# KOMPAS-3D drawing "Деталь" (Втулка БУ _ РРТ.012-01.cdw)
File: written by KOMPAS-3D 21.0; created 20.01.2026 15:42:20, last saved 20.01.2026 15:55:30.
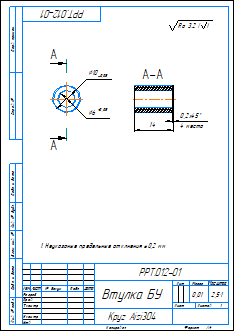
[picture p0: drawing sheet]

Sheet 1: A4, portrait

Document properties: Автор: Alexey; Масса: 0.005513; Полное имя файла: ..\Documents\Bitrix24\Производство\технологии\KazanTarget\эксперименты\ручной ротатор\РРТ.012-01 Втулка БУ\РРТ.012-01 Втулка БУ.m3d

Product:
- Part/product: Деталь
    Масса: 0.005513

Title block, sheet 1: Наименование: Втулка БУ; designation: РРТ.012-01; Материал: Круг Aisi304; Масса: 0,01; Количество листов документа: 1; Форматы листов документа: A4; stored path: C:\Users\Alexey\Desktop\Втулка БУ _ РРТ.012-01.cdw

Views: Вид 1, Слева, Разрез А-А
Referenced files in C:\Users\Alexey\Documents\Bitrix24\Производство\технологии\KazanTarget\эксперименты\ручной ротатор\РРТ.012-01 Втулка БУ\: РРТ.012-01 Втулка БУ.m3d
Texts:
  1. Неуказаные предельные отклнения  0,2 мм
Dimensions and other numbers on the sheet: 6; 10; 14; 0,2; 4 места; 2,5:1; 1; 0,01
